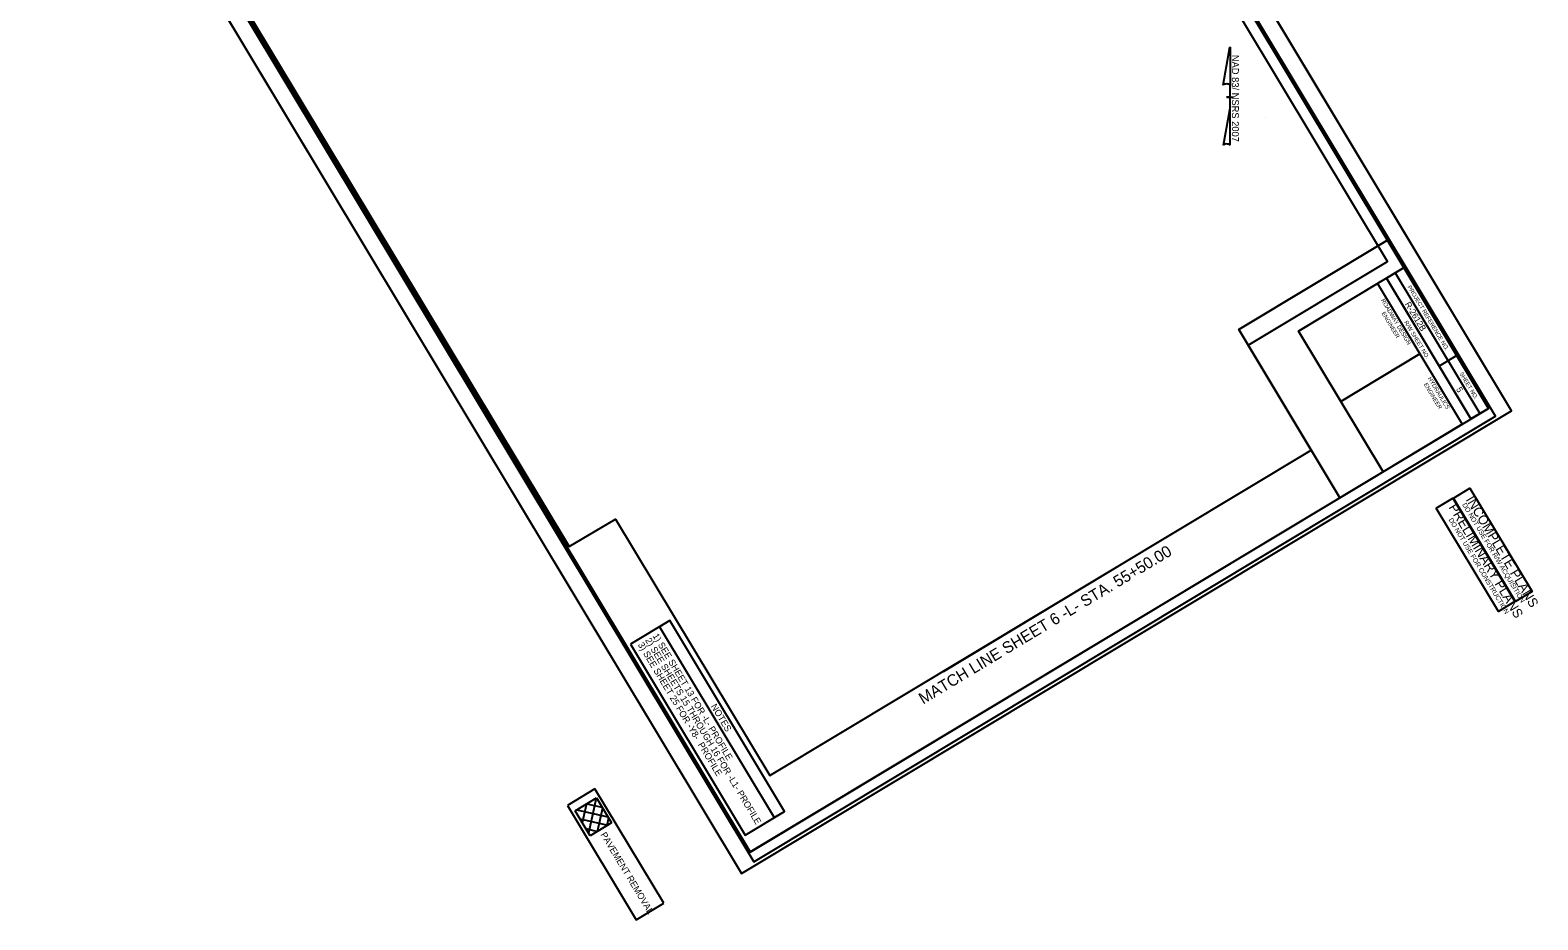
# Model space of a CAD drawing. Extents: x 1780304 to 1782142, y 813409 to 815472.
# Drawn here: x 1780304 to 1782142, y 813409 to 814493 of the extents above; entities that cross this region are included whole.
import ezdxf

# ---------------------------------------------------------------- set-up
doc = ezdxf.new("R2010")
doc.units = 0
for name, color, linetype in [('Matchline', 7, 'Continuous'), ('Matchline Text', 7, 'Continuous'), ('Prop DSN Text', 7, 'Continuous'), ('Prop Grid Mask', 7, 'Continuous'), ('Prop North Arrow NAD83 for Plan Sheets CELL', 7, 'Continuous'), ('Prop Rem of Exist Asph Pvmt', 7, 'Continuous'), ('Sheet Clip Boundary CELL', 7, 'Continuous'), ('Sheet Cutting Line CELL', 7, 'Continuous'), ('Sheet Data Field CELL', 7, 'Continuous'), ('Sheet North Arrow Point CELL', 7, 'Continuous'), ('Sheet Plan CELL', 7, 'Continuous'), ('Sheet Plan Layout CELL', 7, 'Continuous'), ('Sheet Plot Border Inside CELL', 7, 'Continuous'), ('Sheet Plot Border Outside CELL', 7, 'Continuous'), ('Sheet Sticker Incomplete CELL', 7, 'Continuous'), ('Sheet Sticker Preliminary CELL', 7, 'Continuous')]:
    doc.layers.add(name, color=color, linetype=linetype)

msp = doc.modelspace()

# ---------------------------------------------------------------- linework, layer by layer
at = {"layer": 'Matchline'}
for p, q in [((1781206.1, 813584.5), (1781866, 813981)), ((1781417.5, 813711.5), (1781674.6, 813866))]:
    msp.add_line(p, q, dxfattribs=at)
at = {"layer": 'Prop Grid Mask'}
for p, q in [((1780992.8, 813568.2), (1780959.2, 813548)), ((1781076.6, 813428.8), (1780992.8, 813568.2)), ((1780959.2, 813548), (1781042.9, 813408.6)), ((1781042.9, 813408.6), (1781076.6, 813428.8))]:
    msp.add_line(p, q, dxfattribs=at)
for points in [[(1781036, 813744.6), (1781175.8, 813511.8), (1781223.9, 813540.7), (1781084.1, 813773.5)], [(1781071.6, 813766), (1781211.4, 813533.2), (1781223.9, 813540.7), (1781084.1, 813773.5)]]:
    msp.add_lwpolyline(points, close=True, dxfattribs=at)
at = {"layer": 'Prop North Arrow NAD83 for Plan Sheets CELL'}
for p, q in [((1781758.6, 814426.1), (1781766.8, 814472.5)), ((1781766.9, 814472.5), (1781766.8, 814472.5)), ((1781766.9, 814472.5), (1781766.8, 814472.5)), ((1781766.9, 814472.5), (1781766.9, 814424.7)), ((1781766.9, 814399.9), (1781766.9, 814426.1)), ((1781766.9, 814424.7), (1781766.9, 814426)), ((1781766.9, 814399.9), (1781758.5, 814352.6)), ((1781762.9, 814411.5), (1781762.8, 814411.5)), ((1781762.9, 814411.5), (1781770.9, 814411.5)), ((1781766.4, 814411.5), (1781762.9, 814411.5)), ((1781766.9, 814352.8), (1781766.9, 814399.9))]:
    msp.add_line(p, q, dxfattribs=at)
for centre, start_param, end_param in [((1781762.8, 814425.6), 0.216388, 2.908219), ((1781762.8, 814352.4), 0.201328, 3.141593)]:
    msp.add_ellipse(centre, major_axis=(4.23, -0.03), ratio=0.461098, start_param=start_param, end_param=end_param, dxfattribs=at)
at = {"layer": 'Prop Rem of Exist Asph Pvmt'}
for p, q in [((1780968.6, 813541.5), (1780994.9, 813557.3)), ((1780994.4, 813556.8), (1780984.8, 813514.5)), ((1780994.9, 813557.3), (1781013.2, 813526.8)), ((1780986.9, 813510.9), (1780968.6, 813541.5)), ((1780970.7, 813542.8), (1781008.6, 813534.2)), ((1780982.6, 813549.9), (1780977.3, 813526.9)), ((1780983.1, 813550.2), (1781001.1, 813546.1)), ((1781001.9, 813544.8), (1780995.4, 813516)), ((1780974.5, 813531.6), (1781008.5, 813523.9)), ((1780981.6, 813519.8), (1780996.1, 813516.5)), ((1781013.2, 813526.8), (1780986.9, 813510.9)), ((1781009.5, 813533), (1781007.3, 813523.2))]:
    msp.add_line(p, q, dxfattribs=at)
at = {"layer": 'Sheet Clip Boundary CELL'}
msp.add_lwpolyline([(1780454.1, 814707.6), (1780961.4, 813863.6), (1781017.8, 813897.1), (1781206.1, 813584.5), (1781866, 813981), (1781789.1, 814109), (1781958.9, 814211), (1781340.5, 815240.2)], close=True, dxfattribs=at)
at = {"layer": 'Sheet Cutting Line CELL'}
for p, q in [((1782110.1, 814029.1), (1781243, 815472.2)), ((1780304.4, 814908.2), (1781171.5, 813465.2))]:
    msp.add_line(p, q, dxfattribs=at)
at = {"layer": 'Sheet North Arrow Point CELL'}
msp.add_line((1781810.7, 814386.8), (1781810.7, 814386.8), dxfattribs=at)
at = {"layer": 'Sheet Plan CELL'}
for p, q in [((1781968.3, 814197.2), (1782071.3, 814025.7)), ((1781957.5, 814190.7), (1781946.8, 814184.3)), ((1781957.5, 814190.7), (1782060.6, 814019.2)), ((1781957.5, 814190.7), (1782060.6, 814019.2)), ((1781998.4, 814098.5), (1781902, 814040.6)), ((1782043.4, 814096.4), (1782022, 814083.5))]:
    msp.add_line(p, q, dxfattribs=at)
for points in [[(1782082.1, 814032.1), (1781309.5, 815317.9), (1780409.5, 814777.1), (1781182, 813491.3)], [(1780409.5, 814777.1), (1781309.5, 815317.9), (1781979, 814203.6), (1781850.4, 814126.3), (1781953.4, 813954.8), (1781182, 813491.3)], [(1781979, 814203.6), (1782082.1, 814032.1), (1782060.6, 814019.2), (1781957.5, 814190.7)], [(1781946.8, 814184.3), (1781998.4, 814098.5), (1781901.9, 814040.6), (1781850.4, 814126.3)], [(1781998.4, 814098.5), (1782049.9, 814012.8), (1781953.4, 813954.8), (1781901.9, 814040.6)]]:
    msp.add_lwpolyline(points, close=True, dxfattribs=at)
at = {"layer": 'Sheet Plan Layout CELL'}
for points in [[(1781309.5, 815317.9), (1780409.5, 814777.1), (1781182, 813491.4), (1781900.8, 813923.2), (1781777.6, 814128.3), (1781958.8, 814237.2)], [(1781777.6, 814128.3), (1781900.8, 813923.2), (1782082.1, 814032.1), (1781958.8, 814237.2)]]:
    msp.add_lwpolyline(points, close=True, dxfattribs=at)
at = {"layer": 'Sheet Plot Border Inside CELL'}
msp.add_lwpolyline([(1780328.3, 814907.4), (1781186.3, 813479.3), (1782090.6, 814022.7), (1781232.6, 815450.7)], close=True, dxfattribs=at)
at = {"layer": 'Sheet Plot Border Outside CELL'}
msp.add_lwpolyline([(1780304.4, 814908.2), (1781171.5, 813465.2), (1782110.1, 814029.1), (1781243, 815472.2)], close=True, dxfattribs=at)
at = {"layer": 'Sheet Sticker Incomplete CELL'}
msp.add_lwpolyline([(1782039.3, 813922.7), (1782059.4, 813934.8), (1782135.2, 813808.8), (1782115, 813796.7)], close=True, dxfattribs=at)
at = {"layer": 'Sheet Sticker Preliminary CELL'}
msp.add_lwpolyline([(1782018.3, 813910.4), (1782038.5, 813922.5), (1782114.2, 813796.5), (1782094.1, 813784.4)], close=True, dxfattribs=at)

# ---------------------------------------------------------------- texts
at = {"layer": 'Matchline Text'}
msp.add_text('MATCH LINE SHEET 6 -L- STA. 55+50.00', height=14, rotation=31, dxfattribs=at).set_placement((1781392.8, 813671))
at = {"layer": 'Prop DSN Text'}
for s, height, p in [('1) SEE SHEET 13 FOR -L- PROFILE ', 8, (1781062.8, 813754.8)), ('3) SEE SHEET 25 FOR -Y8-  PROFILE', 8, (1781044.8, 813744)), ('2) SEE SHEETS 15 THROUGH 16 FOR -L1- PROFILE', 8, (1781053.8, 813749.4)), ('NOTES', 8.1, (1781133.7, 813669)), ('PAVEMENT REMOVAL', 8, (1780999.3, 813512.6))]:
    msp.add_text(s, height=height, rotation=301, dxfattribs=at).set_placement(p)
at = {"layer": 'Prop North Arrow NAD83 for Plan Sheets CELL'}
msp.add_text('NAD 83/ NSRS 2007', height=8.5, rotation=270, dxfattribs=at).set_placement((1781769.2, 814463))
at = {"layer": 'Sheet Data Field CELL'}
for s, p in [('R-2612B  ', (1781979.7, 814159.2)), ('5', (1782042.1, 814055.4))]:
    msp.add_text(s, height=7.5, rotation=301, dxfattribs=at).set_placement(p)
at = {"layer": 'Sheet Plan CELL'}
for s, p in [('PROJECT REFERENCE NO.', (1781983, 814180.1)), ('ROADWAY DESIGN', (1781950.6, 814163.9)), ('ENGINEER', (1781951.3, 814148)), ('R/W SHEET NO.', (1781979, 814137.1)), ('HYDRAULICS', (1782007.8, 814068.6)), ('SHEET NO.', (1782046.3, 814074.5)), ('ENGINEER', (1782002.9, 814061.3))]:
    msp.add_text(s, height=5, rotation=301, dxfattribs=at).set_placement(p)
at = {"layer": 'Sheet Sticker Incomplete CELL'}
for s, height, p in [('INCOMPLETE PLANS', 11.52, (1782053.9, 813921)), ('DO NOT USE FOR R/W ACQUISITION', 5.76, (1782049.7, 813914.7))]:
    msp.add_text(s, height=height, rotation=301, dxfattribs=at).set_placement(p)
at = {"layer": 'Sheet Sticker Preliminary CELL'}
for s, height, p in [('PRELIMINARY PLANS', 11.52, (1782033, 813911.6)), ('DO NOT USE FOR CONSTRUCTION', 5.76, (1782033.1, 813896.4))]:
    msp.add_text(s, height=height, rotation=301, dxfattribs=at).set_placement(p)

doc.saveas('drawing.dxf')
